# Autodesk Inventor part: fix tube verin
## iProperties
Shininess: 63.0
Length Units: 11269
Angle Units: 11279
Time Units: 11290
Mass Units: 11283
Length Display Precision: 3
Angle Display Precision: 2
Created: 2002-09
Part Number: fix tube verin
Material: Par défaut
Document SubType Name: Modélisation
Designer: Maison
Density: 0.0
Volumn: 0.0
Area: 0.0
PropertySet Name: Model Information
Control State: 0
Master: False
Checked Out: False
Author: Maison
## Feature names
1. Extrusion1
2. Congé2 [Fillet]
3. Extrusion4
4. Extrusion5
5. Perçage4 [Hole]
6. Perçage5 [Hole]
7. Extrusion6
